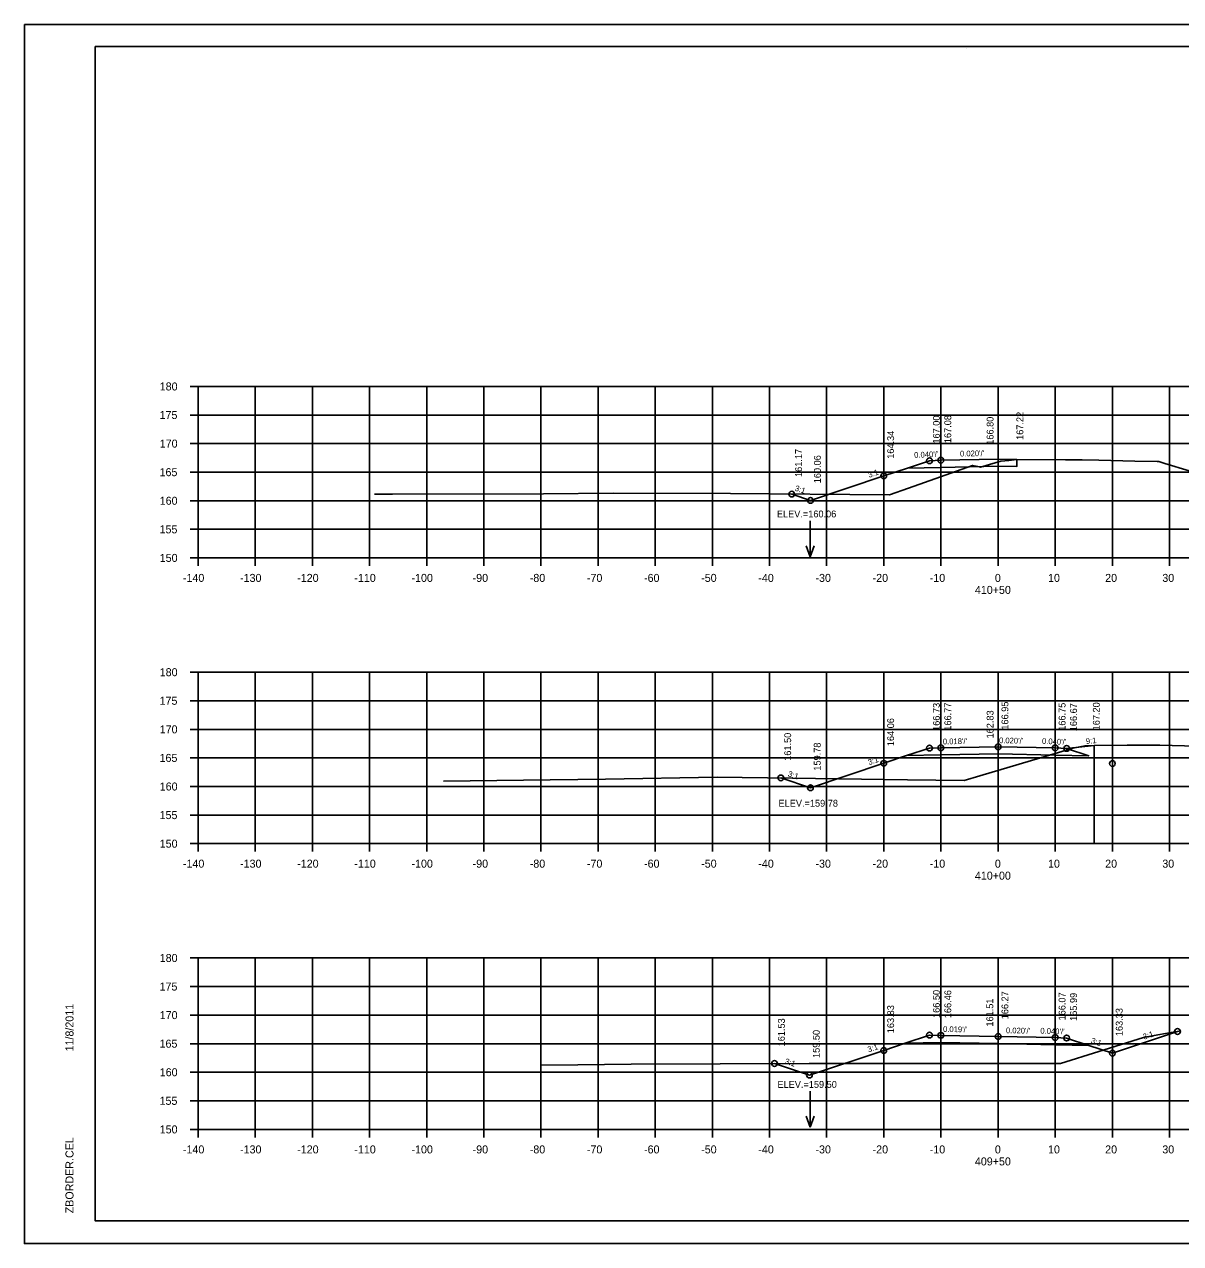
# Model space of a CAD drawing. Extents: x 1368503 to 1373085, y 379840 to 381833.
# Drawn here: x 1372751.7 to 1372954, y 381241.7 to 381455 of the extents above; entities that cross this region are included whole.
import ezdxf

# ---------------------------------------------------------------- set-up
doc = ezdxf.new("R2010")
doc.units = 0
for name, color, linetype in [('S_BRIDGE', 7, 'Continuous'), ('S_EDGE_PAVEMENT', 7, 'Continuous'), ('S_GRAVEL_ROAD', 7, 'Continuous'), ('S_MISC_BOUNDARY', 7, 'Continuous'), ('S_OBSCURES', 7, 'Continuous'), ('S_PHOTO_CENTERS', 7, 'Continuous'), ('S_PHOTO_NOTES', 7, 'Continuous'), ('S_RDW_PT_SYM', 7, 'Continuous'), ('S_SHOULDER', 7, 'Continuous'), ('S_STREAM_ANNOT', 7, 'Continuous'), ('S_TRAILS', 7, 'Continuous'), ('S_TRAILS_ANNOT', 7, 'Continuous')]:
    doc.layers.add(name, color=color, linetype=linetype)

msp = doc.modelspace()

# ---------------------------------------------------------------- linework, layer by layer
at = {"layer": 'S_BRIDGE'}
for p, q in [((1372764.08, 381451.1), (1373080.26, 381451.1)), ((1372764.08, 381245.64), (1372764.08, 381451.1)), ((1372916.6, 381450.84), (1372916.6, 381450.84)), ((1372916.6, 381450.84), (1372916.6, 381450.84)), ((1372764.08, 381245.64), (1372764.08, 381245.64)), ((1373080.26, 381245.64), (1372764.08, 381245.64))]:
    msp.add_line(p, q, dxfattribs=at)
at = {"layer": 'S_EDGE_PAVEMENT'}
for p, q in [((1372780.68, 381391.64), (1372782.08, 381391.64)), ((1372782.08, 381361.64), (1372782.08, 381391.64)), ((1372780.68, 381386.64), (1372782.08, 381386.64)), ((1372780.68, 381381.64), (1372782.08, 381381.64)), ((1372780.68, 381376.64), (1372782.08, 381376.64)), ((1372780.68, 381371.64), (1372782.08, 381371.64)), ((1372780.68, 381366.64), (1372782.08, 381366.64)), ((1372780.68, 381361.64), (1372782.08, 381361.64)), ((1372782.08, 381361.64), (1373062.08, 381361.64)), ((1372782.08, 381360.24), (1372782.08, 381361.64)), ((1372792.08, 381360.24), (1372792.08, 381361.64)), ((1372802.08, 381360.24), (1372802.08, 381361.64)), ((1372812.08, 381360.24), (1372812.08, 381361.64)), ((1372822.08, 381360.24), (1372822.08, 381361.64)), ((1372832.08, 381360.24), (1372832.08, 381361.64)), ((1372842.08, 381360.24), (1372842.08, 381361.64)), ((1372852.08, 381360.24), (1372852.08, 381361.64)), ((1372862.08, 381360.24), (1372862.08, 381361.64)), ((1372872.08, 381360.24), (1372872.08, 381361.64)), ((1372882.08, 381360.24), (1372882.08, 381361.64)), ((1372892.08, 381360.24), (1372892.08, 381361.64)), ((1372902.08, 381360.24), (1372902.08, 381361.64)), ((1372912.08, 381360.24), (1372912.08, 381361.64)), ((1372922.08, 381360.24), (1372922.08, 381361.64)), ((1372932.08, 381360.24), (1372932.08, 381361.64)), ((1372942.08, 381360.24), (1372942.08, 381361.64)), ((1372952.08, 381360.24), (1372952.08, 381361.64)), ((1372780.68, 381341.64), (1372782.08, 381341.64)), ((1372782.08, 381311.64), (1372782.08, 381341.64)), ((1372780.68, 381336.64), (1372782.08, 381336.64)), ((1372780.68, 381331.64), (1372782.08, 381331.64)), ((1372780.68, 381326.64), (1372782.08, 381326.64)), ((1372780.68, 381321.64), (1372782.08, 381321.64)), ((1372780.68, 381316.64), (1372782.08, 381316.64)), ((1372780.68, 381311.64), (1372782.08, 381311.64)), ((1372782.08, 381311.64), (1373062.08, 381311.64)), ((1372782.08, 381310.24), (1372782.08, 381311.64)), ((1372792.08, 381310.24), (1372792.08, 381311.64)), ((1372802.08, 381310.24), (1372802.08, 381311.64)), ((1372812.08, 381310.24), (1372812.08, 381311.64)), ((1372822.08, 381310.24), (1372822.08, 381311.64)), ((1372832.08, 381310.24), (1372832.08, 381311.64)), ((1372842.08, 381310.24), (1372842.08, 381311.64)), ((1372852.08, 381310.24), (1372852.08, 381311.64)), ((1372862.08, 381310.24), (1372862.08, 381311.64)), ((1372872.08, 381310.24), (1372872.08, 381311.64)), ((1372882.08, 381310.24), (1372882.08, 381311.64)), ((1372892.08, 381310.24), (1372892.08, 381311.64)), ((1372902.08, 381310.24), (1372902.08, 381311.64)), ((1372912.08, 381310.24), (1372912.08, 381311.64)), ((1372922.08, 381310.24), (1372922.08, 381311.64)), ((1372932.08, 381310.24), (1372932.08, 381311.64)), ((1372942.08, 381310.24), (1372942.08, 381311.64)), ((1372952.08, 381310.24), (1372952.08, 381311.64)), ((1372780.68, 381291.64), (1372782.08, 381291.64)), ((1372782.08, 381261.64), (1372782.08, 381291.64)), ((1372780.68, 381286.64), (1372782.08, 381286.64)), ((1372780.68, 381281.64), (1372782.08, 381281.64)), ((1372780.68, 381276.64), (1372782.08, 381276.64)), ((1372780.68, 381271.64), (1372782.08, 381271.64)), ((1372780.68, 381266.64), (1372782.08, 381266.64)), ((1372780.68, 381261.64), (1372782.08, 381261.64)), ((1372782.08, 381261.64), (1373062.08, 381261.64)), ((1372782.08, 381260.24), (1372782.08, 381261.64)), ((1372792.08, 381260.24), (1372792.08, 381261.64)), ((1372802.08, 381260.24), (1372802.08, 381261.64)), ((1372812.08, 381260.24), (1372812.08, 381261.64)), ((1372822.08, 381260.24), (1372822.08, 381261.64)), ((1372832.08, 381260.24), (1372832.08, 381261.64)), ((1372842.08, 381260.24), (1372842.08, 381261.64)), ((1372852.08, 381260.24), (1372852.08, 381261.64)), ((1372862.08, 381260.24), (1372862.08, 381261.64)), ((1372872.08, 381260.24), (1372872.08, 381261.64)), ((1372882.08, 381260.24), (1372882.08, 381261.64)), ((1372892.08, 381260.24), (1372892.08, 381261.64)), ((1372902.08, 381260.24), (1372902.08, 381261.64)), ((1372912.08, 381260.24), (1372912.08, 381261.64)), ((1372922.08, 381260.24), (1372922.08, 381261.64)), ((1372932.08, 381260.24), (1372932.08, 381261.64)), ((1372942.08, 381260.24), (1372942.08, 381261.64)), ((1372952.08, 381260.24), (1372952.08, 381261.64))]:
    msp.add_line(p, q, dxfattribs=at)
at = {"layer": 'S_GRAVEL_ROAD'}
for p, q in [((1372889.17, 381368.13), (1372889.17, 381361.85)), ((1372889.17, 381361.85), (1372888.47, 381363.77)), ((1372889.17, 381361.85), (1372889.87, 381363.77)), ((1372889.17, 381268.31), (1372889.17, 381262.02)), ((1372889.17, 381262.02), (1372888.47, 381263.95)), ((1372889.17, 381262.02), (1372889.87, 381263.95))]:
    msp.add_line(p, q, dxfattribs=at)
at = {"layer": 'S_MISC_BOUNDARY'}
for points in [[(1372812.96, 381372.77), (1372816.09, 381372.78), (1372842.54, 381372.85), (1372854.72, 381372.97), (1372875.23, 381372.89), (1372903.06, 381372.66), (1372906.38, 381373.86), (1372917.61, 381377.81), (1372918.56, 381377.61), (1372919.01, 381377.52), (1372920.56, 381377.98), (1372922.58, 381378.59), (1372923.95, 381378.71), (1372925.34, 381378.84), (1372933.85, 381378.81), (1372936.77, 381378.81), (1372939.74, 381378.73), (1372946.03, 381378.55), (1372949.94, 381378.5), (1372950.19, 381378.49), (1372951.27, 381378.17), (1372955.53, 381376.86)], [(1372825.05, 381322.6), (1372843.7, 381322.81), (1372853.37, 381322.92), (1372872.93, 381323.25), (1372886.09, 381323.12), (1372906.24, 381322.81), (1372916.14, 381322.69), (1372918.91, 381323.52), (1372932.68, 381327.6), (1372935.17, 381328.37), (1372937.3, 381328.77), (1372938.88, 381328.84), (1372944.66, 381328.87), (1372950.39, 381328.88), (1372956.88, 381328.72)], [(1372842.17, 381272.87), (1372848.52, 381272.94), (1372857.87, 381273.05), (1372889.02, 381273.2), (1372904.57, 381273.15), (1372932.98, 381273.16), (1372939.72, 381275.3), (1372947.52, 381277.72), (1372950.02, 381278.17), (1372954.07, 381278.87)]]:
    msp.add_lwpolyline(points, dxfattribs=at)
at = {"layer": 'S_OBSCURES'}
for points in [[(1372925.34, 381378.86), (1372925.34, 381377.61), (1372922.08, 381377.67), (1372912.08, 381377.47), (1372906.22, 381377.36)], [(1372934.08, 381328.31), (1372937.94, 381327.02), (1372932.08, 381327.14), (1372922.08, 381327.34), (1372912.08, 381327.16), (1372906.08, 381327.04)], [(1372937.94, 381276.34), (1372932.08, 381276.46), (1372922.08, 381276.66), (1372912.08, 381276.85), (1372905.84, 381276.73)]]:
    msp.add_lwpolyline(points, dxfattribs=at)
at = {"layer": 'S_PHOTO_CENTERS'}
for p, q in [((1372782.08, 381391.64), (1373062.08, 381391.64)), ((1372782.08, 381361.64), (1372782.08, 381391.64)), ((1372792.08, 381361.64), (1372792.08, 381391.64)), ((1372802.08, 381361.64), (1372802.08, 381391.64)), ((1372812.08, 381361.64), (1372812.08, 381391.64)), ((1372822.08, 381361.64), (1372822.08, 381391.64)), ((1372832.08, 381361.64), (1372832.08, 381391.64)), ((1372842.08, 381361.64), (1372842.08, 381391.64)), ((1372852.08, 381361.64), (1372852.08, 381391.64)), ((1372862.08, 381361.64), (1372862.08, 381391.64)), ((1372872.08, 381361.64), (1372872.08, 381391.64)), ((1372882.08, 381361.64), (1372882.08, 381391.64)), ((1372892.08, 381361.64), (1372892.08, 381391.64)), ((1372902.08, 381361.64), (1372902.08, 381391.64)), ((1372912.08, 381361.64), (1372912.08, 381391.64)), ((1372922.08, 381361.64), (1372922.08, 381391.64)), ((1372932.08, 381361.64), (1372932.08, 381391.64)), ((1372942.08, 381361.64), (1372942.08, 381391.64)), ((1372952.08, 381361.64), (1372952.08, 381391.64)), ((1372782.08, 381386.64), (1373062.08, 381386.64)), ((1372782.08, 381381.64), (1373062.08, 381381.64)), ((1372782.08, 381376.64), (1373062.08, 381376.64)), ((1372782.08, 381371.64), (1373062.08, 381371.64)), ((1372782.08, 381366.64), (1373062.08, 381366.64)), ((1372782.08, 381361.64), (1373062.08, 381361.64)), ((1372782.08, 381341.64), (1373062.08, 381341.64)), ((1372782.08, 381311.64), (1372782.08, 381341.64)), ((1372792.08, 381311.64), (1372792.08, 381341.64)), ((1372802.08, 381311.64), (1372802.08, 381341.64)), ((1372812.08, 381311.64), (1372812.08, 381341.64)), ((1372822.08, 381311.64), (1372822.08, 381341.64)), ((1372832.08, 381311.64), (1372832.08, 381341.64)), ((1372842.08, 381311.64), (1372842.08, 381341.64)), ((1372852.08, 381311.64), (1372852.08, 381341.64)), ((1372862.08, 381311.64), (1372862.08, 381341.64)), ((1372872.08, 381311.64), (1372872.08, 381341.64)), ((1372882.08, 381311.64), (1372882.08, 381341.64)), ((1372892.08, 381311.64), (1372892.08, 381341.64)), ((1372902.08, 381311.64), (1372902.08, 381341.64)), ((1372912.08, 381311.64), (1372912.08, 381341.64)), ((1372922.08, 381311.64), (1372922.08, 381341.64)), ((1372932.08, 381311.64), (1372932.08, 381341.64)), ((1372942.08, 381311.64), (1372942.08, 381341.64)), ((1372952.08, 381311.64), (1372952.08, 381341.64)), ((1372782.08, 381336.64), (1373062.08, 381336.64)), ((1372782.08, 381331.64), (1373062.08, 381331.64)), ((1372782.08, 381326.64), (1373062.08, 381326.64)), ((1372782.08, 381321.64), (1373062.08, 381321.64)), ((1372782.08, 381316.64), (1373062.08, 381316.64)), ((1372782.08, 381311.64), (1373062.08, 381311.64)), ((1372782.08, 381291.64), (1373062.08, 381291.64)), ((1372782.08, 381261.64), (1372782.08, 381291.64)), ((1372792.08, 381261.64), (1372792.08, 381291.64)), ((1372802.08, 381261.64), (1372802.08, 381291.64)), ((1372812.08, 381261.64), (1372812.08, 381291.64)), ((1372822.08, 381261.64), (1372822.08, 381291.64)), ((1372832.08, 381261.64), (1372832.08, 381291.64)), ((1372842.08, 381261.64), (1372842.08, 381291.64)), ((1372852.08, 381261.64), (1372852.08, 381291.64)), ((1372862.08, 381261.64), (1372862.08, 381291.64)), ((1372872.08, 381261.64), (1372872.08, 381291.64)), ((1372882.08, 381261.64), (1372882.08, 381291.64)), ((1372892.08, 381261.64), (1372892.08, 381291.64)), ((1372902.08, 381261.64), (1372902.08, 381291.64)), ((1372912.08, 381261.64), (1372912.08, 381291.64)), ((1372922.08, 381261.64), (1372922.08, 381291.64)), ((1372932.08, 381261.64), (1372932.08, 381291.64)), ((1372942.08, 381261.64), (1372942.08, 381291.64)), ((1372952.08, 381261.64), (1372952.08, 381291.64)), ((1372782.08, 381286.64), (1373062.08, 381286.64)), ((1372782.08, 381281.64), (1373062.08, 381281.64)), ((1372782.08, 381276.64), (1373062.08, 381276.64)), ((1372782.08, 381271.64), (1373062.08, 381271.64)), ((1372782.08, 381266.64), (1373062.08, 381266.64)), ((1372782.08, 381261.64), (1373062.08, 381261.64))]:
    msp.add_line(p, q, dxfattribs=at)
at = {"layer": 'S_PHOTO_NOTES'}
for p, q in [((1372751.68, 381454.99), (1373085.01, 381454.99)), ((1372938.88, 381311.64), (1372938.88, 381328.84)), ((1372751.68, 381241.66), (1373085.01, 381241.66))]:
    msp.add_line(p, q, dxfattribs=at)
for points in [[(1372751.67, 381454.99), (1373085.01, 381454.99), (1373085.01, 381241.66), (1372751.67, 381241.66)], [(1372998, 381451.1), (1372998, 381441.22), (1373033.73, 381441.22), (1373033.73, 381438.3), (1373056.93, 381438.3), (1373056.93, 381413.97), (1373080.26, 381413.97), (1373080.26, 381245.64), (1372764.08, 381245.64), (1372764.08, 381451.1)]]:
    msp.add_lwpolyline(points, close=True, dxfattribs=at)
for centre in [(1372910.08, 381378.64), (1372912.08, 381378.72), (1372902.08, 381375.98), (1372885.96, 381372.8), (1372889.26, 381371.7), (1372910.08, 381328.37), (1372912.08, 381328.41), (1372922.08, 381328.59), (1372932.08, 381328.39), (1372934.08, 381328.31), (1372902.08, 381325.7), (1372942.08, 381325.65), (1372884.06, 381323.14), (1372889.23, 381321.42), (1372953.48, 381278.77), (1372910.08, 381278.14), (1372912.08, 381278.1), (1372922.08, 381277.91), (1372932.08, 381277.71), (1372934.08, 381277.63), (1372902.08, 381275.47), (1372942.08, 381274.96), (1372882.96, 381273.17), (1372889.06, 381271.14)]:
    msp.add_circle(centre, 0.5, dxfattribs=at)
at = {"layer": 'S_STREAM_ANNOT'}
for points in [[(1372885.96, 381372.8), (1372889.26, 381371.7), (1372902.08, 381375.98), (1372906.22, 381377.36), (1372910.08, 381378.64), (1372912.08, 381378.72), (1372922.08, 381378.92), (1372925.34, 381378.86)], [(1372884.06, 381323.14), (1372889.23, 381321.42), (1372902.08, 381325.7), (1372906.08, 381327.04), (1372910.08, 381328.37), (1372912.08, 381328.41), (1372922.08, 381328.59), (1372932.08, 381328.39), (1372934.08, 381328.31), (1372938.88, 381328.84)], [(1372882.96, 381273.17), (1372889.06, 381271.14), (1372902.08, 381275.47), (1372905.84, 381276.73), (1372910.08, 381278.14), (1372912.08, 381278.1), (1372922.08, 381277.91), (1372932.08, 381277.71), (1372934.08, 381277.63), (1372937.94, 381276.34), (1372942.08, 381274.96), (1372953.48, 381278.77)]]:
    msp.add_lwpolyline(points, dxfattribs=at)

# ---------------------------------------------------------------- texts
at = {"layer": 'S_BRIDGE'}
for s, p in [('11/8/2011', (1372760.27, 381275.28)), ('ZBORDER.CEL', (1372760.27, 381246.96))]:
    msp.add_text(s, height=1.4, rotation=90, dxfattribs=at).set_placement(p)
at = {"layer": 'S_GRAVEL_ROAD'}
for s, p in [('ELEV.=160.06', (1372883.37, 381368.73)), ('ELEV.=159.78', (1372883.66, 381318.11)), ('ELEV.=159.50', (1372883.47, 381268.91))]:
    msp.add_text(s, height=1.2, dxfattribs=at).set_placement(p)
at = {"layer": 'S_RDW_PT_SYM'}
for s, rotation, p in [("0.040'/'", 2.2906, (1372907.41, 381379.14)), ("0.020'/'", 1.1458, (1372915.42, 381379.38)), ('3:1', 18.4339, (1372899.51, 381375.65)), ('3:1', 341.5668, (1372886.42, 381373.44)), ("0.018'/'", 1.0596, (1372912.42, 381329.01)), ("0.020'/'", 358.8542, (1372922.23, 381329.22)), ("0.040'/'", 357.7094, (1372929.75, 381329.1)), ('9:1', 6.0928, (1372937.49, 381329.05)), ('3:1', 18.4339, (1372899.5, 381325.37)), ('3:1', 341.5668, (1372885.21, 381323.45)), ("0.019'/'", 358.9055, (1372912.44, 381278.7)), ("0.020'/'", 358.8542, (1372923.44, 381278.48)), ("0.040'/'", 357.7094, (1372929.46, 381278.42)), ('3:1', 341.5651, (1372938.24, 381276.77)), ('3:1', 18.4332, (1372947.62, 381277.34)), ('3:1', 18.4339, (1372899.41, 381275.11)), ('3:1', 341.5668, (1372884.67, 381273.17))]:
    msp.add_text(s, height=1, rotation=rotation, dxfattribs=at).set_placement(p)
at = {"layer": 'S_SHOULDER'}
for s, p in [('167.00', (1372911.88, 381381.64)), ('167.08', (1372913.88, 381381.72)), ('167.22', (1372926.5, 381382.29)), ('164.34', (1372903.88, 381378.98)), ('161.17', (1372887.76, 381375.8)), ('160.06', (1372891.06, 381374.7)), ('166.73', (1372911.88, 381331.37)), ('166.77', (1372913.88, 381331.41)), ('166.95', (1372923.88, 381331.59)), ('166.75', (1372933.88, 381331.39)), ('166.67', (1372935.88, 381331.31)), ('167.20', (1372939.87, 381331.47)), ('164.06', (1372903.88, 381328.7)), ('161.50', (1372885.86, 381326.14)), ('159.78', (1372891.03, 381324.42)), ('166.50', (1372911.88, 381281.14)), ('166.46', (1372913.88, 381281.1)), ('166.27', (1372923.88, 381280.91)), ('166.07', (1372933.88, 381280.71)), ('165.99', (1372935.88, 381280.63)), ('163.83', (1372903.88, 381278.47)), ('163.33', (1372943.88, 381277.96)), ('161.53', (1372884.76, 381276.17)), ('159.50', (1372890.86, 381274.14))]:
    msp.add_text(s, height=1.2, rotation=90, dxfattribs=at).set_placement(p)
at = {"layer": 'S_TRAILS'}
for s, p in [('180', (1372775.36, 381390.94)), ('175', (1372775.33, 381385.94)), ('170', (1372775.36, 381380.94)), ('165', (1372775.33, 381375.94)), ('160', (1372775.36, 381370.94)), ('155', (1372775.33, 381365.94)), ('150', (1372775.36, 381360.94)), ('-140', (1372779.42, 381357.44)), ('-130', (1372789.42, 381357.44)), ('-120', (1372799.42, 381357.44)), ('-110', (1372809.42, 381357.44)), ('-100', (1372819.42, 381357.44)), ('-90', (1372830.12, 381357.44)), ('-80', (1372840.12, 381357.44)), ('-70', (1372850.12, 381357.44)), ('-60', (1372860.12, 381357.44)), ('-50', (1372870.12, 381357.44)), ('-40', (1372880.12, 381357.44)), ('-30', (1372890.12, 381357.44)), ('-20', (1372900.12, 381357.44)), ('-10', (1372910.12, 381357.44)), ('0', (1372921.52, 381357.44)), ('10', (1372930.82, 381357.44)), ('20', (1372940.82, 381357.44)), ('30', (1372950.82, 381357.44)), ('410+50', (1372918.02, 381355.34)), ('180', (1372775.36, 381340.94)), ('175', (1372775.33, 381335.94)), ('170', (1372775.36, 381330.94)), ('165', (1372775.33, 381325.94)), ('160', (1372775.36, 381320.94)), ('155', (1372775.33, 381315.94)), ('150', (1372775.36, 381310.94)), ('-140', (1372779.42, 381307.44)), ('-130', (1372789.42, 381307.44)), ('-120', (1372799.42, 381307.44)), ('-110', (1372809.42, 381307.44)), ('-100', (1372819.42, 381307.44)), ('-90', (1372830.12, 381307.44)), ('-80', (1372840.12, 381307.44)), ('-70', (1372850.12, 381307.44)), ('-60', (1372860.12, 381307.44)), ('-50', (1372870.12, 381307.44)), ('-40', (1372880.12, 381307.44)), ('-30', (1372890.12, 381307.44)), ('-20', (1372900.12, 381307.44)), ('-10', (1372910.12, 381307.44)), ('0', (1372921.52, 381307.44)), ('10', (1372930.82, 381307.44)), ('20', (1372940.82, 381307.44)), ('30', (1372950.82, 381307.44)), ('410+00', (1372918.02, 381305.34)), ('180', (1372775.36, 381290.94)), ('175', (1372775.33, 381285.94)), ('170', (1372775.36, 381280.94)), ('165', (1372775.33, 381275.94)), ('160', (1372775.36, 381270.94)), ('155', (1372775.33, 381265.94)), ('150', (1372775.36, 381260.94)), ('-140', (1372779.42, 381257.44)), ('-130', (1372789.42, 381257.44)), ('-120', (1372799.42, 381257.44)), ('-110', (1372809.42, 381257.44)), ('-100', (1372819.42, 381257.44)), ('-90', (1372830.12, 381257.44)), ('-80', (1372840.12, 381257.44)), ('-70', (1372850.12, 381257.44)), ('-60', (1372860.12, 381257.44)), ('-50', (1372870.12, 381257.44)), ('-40', (1372880.12, 381257.44)), ('-30', (1372890.12, 381257.44)), ('-20', (1372900.12, 381257.44)), ('-10', (1372910.12, 381257.44)), ('0', (1372921.52, 381257.44)), ('10', (1372930.82, 381257.44)), ('20', (1372940.82, 381257.44)), ('30', (1372950.82, 381257.44)), ('409+50', (1372918.02, 381255.34))]:
    msp.add_text(s, height=1.4, dxfattribs=at).set_placement(p)
at = {"layer": 'S_TRAILS_ANNOT'}
for s, p in [('166.80', (1372921.28, 381381.44)), ('162.83', (1372921.28, 381330.05)), ('161.51', (1372921.23, 381279.63))]:
    msp.add_text(s, height=1.2, rotation=90, dxfattribs=at).set_placement(p)

doc.saveas('drawing.dxf')
